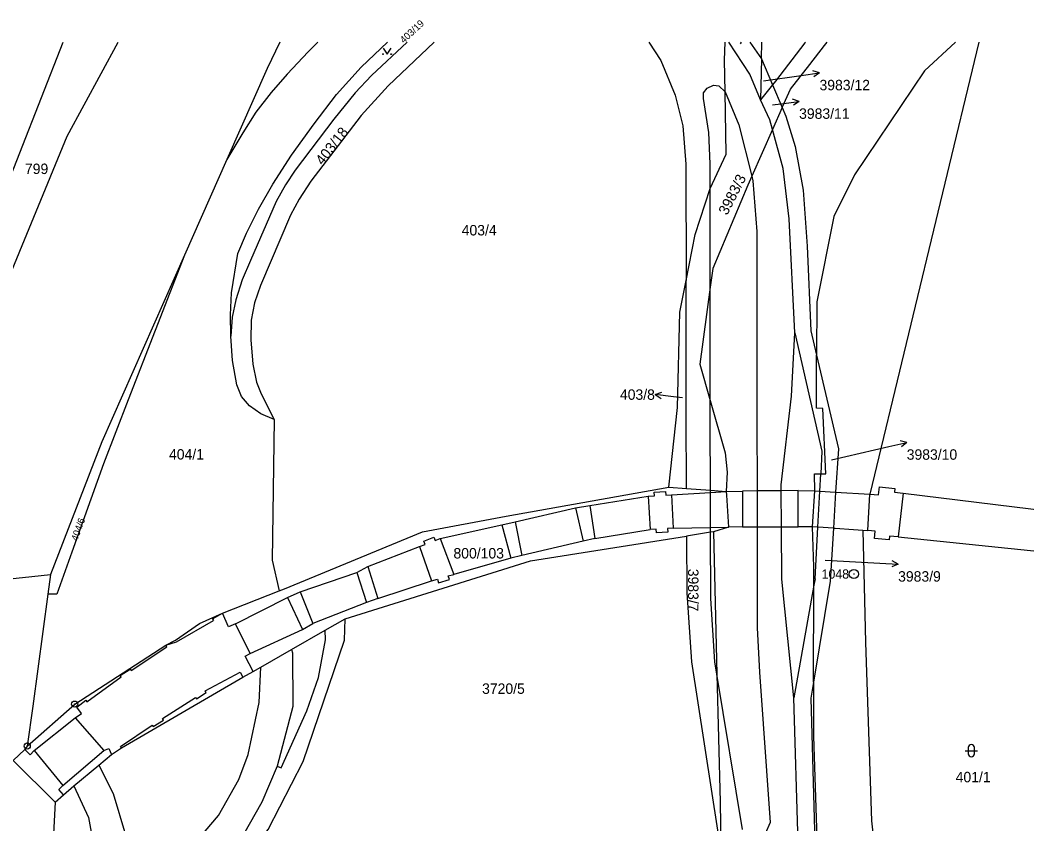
# Model space of a CAD drawing. Extents: x -747779 to -747197, y -965543 to -964919.
# Drawn here: x -747660.7 to -747496.8, y -965049.6 to -964918.7 of the extents above; entities that cross this region are included whole.
import ezdxf

# ---------------------------------------------------------------- set-up
doc = ezdxf.new("R2010")
doc.units = 0
for name, color, linetype in [('Hranice parcel', 7, 'Continuous'), ('Parcelní čísla', 7, 'Continuous'), ('Pop  PČ popisy', 7, 'Continuous'), ('Vnitřní kresba', 7, 'Continuous'), ('Značky bodu BP', 7, 'Continuous'), ('Značky kultur', 7, 'Continuous')]:
    doc.layers.add(name, color=color, linetype=linetype)

msp = doc.modelspace()

# ---------------------------------------------------------------- linework, layer by layer
at = {"layer": 'Hranice parcel'}
for p, q in [((-747539.99, -964924.99), (-747540.12, -964931.65)), ((-747539.99, -964924.99), (-747538.17, -964929.23)), ((-747538.17, -964929.23), (-747540.12, -964931.65)), ((-747538.17, -964929.23), (-747536.59, -964932.93)), ((-747536.59, -964932.93), (-747538.19, -964936.51)), ((-747626.99, -964941.37), (-747633.9, -964956.97)), ((-747555.06, -964994.76), (-747552.2, -964994.96))]:
    msp.add_line(p, q, dxfattribs=at)
for points in [[(-747681.46, -965000.29), (-747680.95, -964999.09), (-747672.35, -964972.3), (-747664.27, -964949.29), (-747653.66, -964922.25)], [(-747679.51, -965002.12), (-747679.42, -965001.69), (-747652.99, -964937.55), (-747644.69, -964922.25)], [(-747618.4, -964922.25), (-747620.44, -964926.57), (-747626.99, -964941.37)], [(-747612.2, -964922.25), (-747613.78, -964923.86), (-747617.18, -964927.46), (-747619.82, -964930.48), (-747622.28, -964933.68), (-747624.41, -964937.05), (-747626.99, -964941.37)], [(-747626.36, -964970.12), (-747626.42, -964966.65), (-747626.24, -964963.07), (-747625.23, -964956.7), (-747623.82, -964953.37), (-747621.85, -964949.45), (-747619.54, -964945.4), (-747616.5, -964940.69), (-747612.82, -964935.54), (-747609.15, -964930.81), (-747605.17, -964926.31), (-747600.85, -964922.25)], [(-747597.67, -964922.25), (-747603.48, -964927.68), (-747606.12, -964930.54), (-747609.57, -964934.8), (-747615.87, -964943.12), (-747617.46, -964945.5), (-747618.98, -964948.21), (-747623.16, -964957.81), (-747624.52, -964960.99), (-747625.54, -964964.21), (-747626.17, -964967.05), (-747626.36, -964970.12)], [(-747593.26, -964922.25), (-747600.76, -964929.37), (-747605.14, -964934.21), (-747613.35, -964944.89), (-747615.24, -964947.83), (-747616.64, -964950.46), (-747621.52, -964961.9), (-747622.5, -964964.72), (-747623.07, -964967.52), (-747623.12, -964970.73), (-747622.76, -964974.72), (-747622.16, -964977.65), (-747621.45, -964979.51), (-747619.33, -964983.74)], [(-747558.33, -964922.25), (-747556.34, -964925.25), (-747554.01, -964930.9), (-747552.8, -964935.88), (-747552.27, -964942.11), (-747552.26, -964961.06)], [(-747552.26, -964961.06), (-747550.79, -964953.59), (-747548.32, -964946.08), (-747545.72, -964940.48), (-747545.91, -964930.33), (-747546, -964925.2), (-747545.87, -964922.25)], [(-747540.12, -964931.65), (-747541.88, -964927.49), (-747545.31, -964922.25)], [(-747541.85, -964922.25), (-747539.99, -964924.99)], [(-747539.99, -964924.99), (-747539.94, -964922.25)], [(-747532.8, -964922.25), (-747532.89, -964922.36), (-747537.7, -964928.64), (-747538.17, -964929.23)], [(-747536.59, -964932.93), (-747535.26, -964929.94), (-747532.12, -964925.89), (-747529.73, -964922.8), (-747529.3, -964922.25)], [(-747508.39, -964922.25), (-747513.42, -964926.91), (-747524.82, -964943.86), (-747525.34, -964944.9), (-747527.79, -964949.82), (-747528.21, -964950.66), (-747530.97, -964964.56), (-747531.01, -964973.24)], [(-747538.19, -964936.51), (-747538.62, -964934.92), (-747540.12, -964931.65)], [(-747536.59, -964932.93), (-747535.99, -964934.33), (-747534.51, -964939.26), (-747533.21, -964946.39), (-747532.52, -964955.47), (-747531.93, -964969.25), (-747531.01, -964973.24)], [(-747538.19, -964936.51), (-747541.56, -964944.09), (-747542.21, -964945.54), (-747547.91, -964959.15), (-747548.32, -964962.14), (-747550.02, -964974.69), (-747548.31, -964980.62), (-747545.86, -964989.14), (-747545.55, -964992.32), (-747545.72, -964995.42)], [(-747513.05, -965203.34), (-747515.92, -965191.31), (-747520.21, -965170.52), (-747525.67, -965137.7), (-747528.61, -965118.1), (-747531.3, -965092.39), (-747532.87, -965073.71), (-747533.98, -965052.7), (-747534.7, -965029.05), (-747536.67, -965009.71), (-747536.72, -965001.18), (-747536.76, -964995.31), (-747536.77, -964994.35), (-747535.07, -964979.91), (-747534.55, -964969.6), (-747535.47, -964951.02), (-747536.46, -964942.86), (-747538.19, -964936.51)], [(-747633.9, -964956.97), (-747638.69, -964969.23), (-747643.08, -964980.52), (-747647.08, -964990.95), (-747652.25, -965005.33), (-747654.67, -965012.15), (-747656.14, -965012.16)], [(-747633.9, -964956.97), (-747647.36, -964987.37), (-747655.7, -965008.96), (-747656.14, -965012.16)], [(-747555.06, -964994.76), (-747553.66, -964981.74), (-747553.27, -964966.23), (-747552.26, -964961.06)], [(-747552.2, -964994.96), (-747552.24, -964983.14), (-747552.26, -964961.06)], [(-747619.33, -964983.74), (-747621.48, -964982.79), (-747623.33, -964981.51), (-747624.65, -964979.96), (-747625.39, -964978.05), (-747626.07, -964974.09), (-747626.36, -964970.12)], [(-747531.69, -965001.21), (-747531.31, -964995.33), (-747531.36, -964992.55), (-747530.33, -964992.56), (-747529.52, -964992.56), (-747530.01, -964981.9), (-747531.04, -964981.86), (-747531.01, -964973.24)], [(-747531.01, -964973.24), (-747527.46, -964988.49), (-747527.9, -964995.54), (-747528.26, -965001.42)], [(-747619.33, -964983.74), (-747619.61, -965006.6), (-747618.52, -965011.63)], [(-747618.52, -965011.63), (-747617.61, -965011.27), (-747595.16, -965002.01), (-747581.54, -964999.46), (-747555.06, -964994.76)], [(-747552.2, -964994.96), (-747548.28, -964995.24), (-747545.72, -964995.42)], [(-747545.72, -964995.42), (-747545.68, -964996.06), (-747545.36, -965001.27), (-747547.8, -965002.01)], [(-747547.8, -965002.01), (-747548.27, -965002.08), (-747552.17, -965002.7)], [(-747547.8, -965002.01), (-747547.22, -965025.19), (-747546.7, -965046.04), (-747546.54, -965056.95)], [(-747531.5, -965026.48), (-747531.44, -965010.69), (-747531.43, -965007.69), (-747531.69, -965001.21)], [(-747528.26, -965001.42), (-747530.8, -965001.26), (-747531.69, -965001.21)], [(-747528.26, -965001.42), (-747528.79, -965010.06), (-747531.5, -965026.48)], [(-747528.26, -965001.42), (-747527.97, -965001.44), (-747524.98, -965001.63), (-747523.47, -965001.72), (-747523.04, -965020.06), (-747522.04, -965049.05), (-747520.57, -965062.57), (-747513.95, -965097.88), (-747505.52, -965130.78), (-747493.77, -965163.26), (-747487.95, -965176.49)], [(-747607.76, -965016.2), (-747577.6, -965006.72), (-747552.17, -965002.7)], [(-747552.17, -965002.7), (-747552.14, -965011.96), (-747551.37, -965023.19), (-747547.13, -965050.59), (-747546.54, -965056.95)], [(-747659.51, -965036.9), (-747651.78, -965030.07), (-747636.97, -965020.46), (-747635.38, -965019.64), (-747631.49, -965016.92), (-747627.72, -965015.27), (-747618.52, -965011.63)], [(-747656.14, -965012.16), (-747658.62, -965030.4), (-747659.51, -965036.9)], [(-747654.95, -965046.06), (-747653.6, -965044.82), (-747651.92, -965043.4), (-747647.86, -965039.99), (-747645.81, -965038.26), (-747644.18, -965037.21), (-747624.43, -965025.68), (-747622.72, -965024.74), (-747621.47, -965024.03), (-747616.49, -965021.18), (-747610.98, -965018.03), (-747607.76, -965016.2)], [(-747638.39, -965075.25), (-747631.31, -965064.26), (-747625.79, -965057.37), (-747620.28, -965050.49), (-747614.58, -965039.39), (-747607.88, -965019.66), (-747607.76, -965016.2)], [(-747531.5, -965026.48), (-747531.53, -965035.27), (-747530.45, -965066.92)], [(-747659.51, -965036.9), (-747659.91, -965037.48), (-747661.82, -965039.23), (-747654.95, -965046.06)], [(-747654.95, -965046.06), (-747656.17, -965068.62), (-747656.64, -965070.56)]]:
    msp.add_lwpolyline(points, dxfattribs=at)
at = {"layer": 'Pop  PČ popisy'}
for p, q in [((-747543.4, -964922.54), (-747543.22, -964922.25)), ((-747539.65, -964928.55), (-747533.5, -964927.69)), ((-747533.5, -964927.69), (-747530.53, -964927.27)), ((-747530.53, -964927.27), (-747531.59, -964926.92)), ((-747530.53, -964927.27), (-747531.45, -964927.91)), ((-747533.85, -964931.93), (-747534.91, -964931.56)), ((-747538.17, -964932.47), (-747536.83, -964932.3)), ((-747536.83, -964932.3), (-747533.85, -964931.93)), ((-747533.85, -964931.93), (-747534.78, -964932.55)), ((-747557.26, -964979.65), (-747556.2, -964979.28)), ((-747554.28, -964980.02), (-747557.26, -964979.65)), ((-747557.26, -964979.65), (-747556.33, -964980.27)), ((-747552.81, -964980.19), (-747554.28, -964980.02)), ((-747519.25, -964988.11), (-747516.33, -964987.44)), ((-747516.33, -964987.44), (-747517.41, -964987.17)), ((-747516.33, -964987.44), (-747517.19, -964988.15)), ((-747528.58, -964990.26), (-747519.25, -964988.11)), ((-747529.59, -965006.64), (-747520.73, -965007.13)), ((-747520.73, -965007.13), (-747517.73, -965007.29)), ((-747517.73, -965007.29), (-747518.71, -965006.73)), ((-747517.73, -965007.29), (-747518.76, -965007.73))]:
    msp.add_line(p, q, dxfattribs=at)
at = {"layer": 'Vnitřní kresba'}
for p, q in [((-747504.6, -964922.25), (-747522.32, -964995.87)), ((-747549.39, -964930.54), (-747548.81, -964929.74)), ((-747548.81, -964929.74), (-747547.79, -964929.28)), ((-747547.79, -964929.28), (-747546.93, -964929.4)), ((-747546.93, -964929.4), (-747545.91, -964930.33)), ((-747549.42, -964931.45), (-747549.39, -964930.54)), ((-747548.55, -964936.99), (-747549.42, -964931.45)), ((-747545.91, -964930.33), (-747543.68, -964935.74)), ((-747543.68, -964935.74), (-747541.56, -964944.09)), ((-747548.32, -964942.08), (-747548.55, -964936.99)), ((-747548.32, -964946.08), (-747548.32, -964942.08)), ((-747541.56, -964944.09), (-747541.37, -964944.85)), ((-747541.37, -964944.85), (-747540.75, -964953.1)), ((-747548.32, -964962.14), (-747548.32, -964946.08)), ((-747540.75, -964953.1), (-747540.71, -964983.81)), ((-747548.31, -964980.62), (-747548.32, -964962.14)), ((-747534.55, -964969.6), (-747530.13, -964988.87)), ((-747548.31, -964984.22), (-747548.31, -964980.62)), ((-747548.28, -964995.24), (-747548.31, -964984.22)), ((-747540.71, -964983.81), (-747540.69, -964995.35)), ((-747530.13, -964988.87), (-747530.33, -964992.56)), ((-747530.48, -964995.38), (-747530.33, -964992.56)), ((-747557.43, -964995.56), (-747555.6, -964995.46)), ((-747557.4, -964996.16), (-747557.43, -964995.56)), ((-747555.6, -964995.46), (-747555.57, -964996.06)), ((-747554.65, -964996.01), (-747548.28, -964995.59)), ((-747548.28, -964995.59), (-747548.28, -964995.24)), ((-747548.28, -964995.59), (-747545.72, -964995.42)), ((-747548.27, -965001.32), (-747548.28, -964995.59)), ((-747545.72, -964995.42), (-747543.05, -964995.37)), ((-747540.69, -964995.35), (-747543.05, -964995.37)), ((-747543.05, -964995.37), (-747543.05, -965001.2)), ((-747536.76, -964995.31), (-747540.69, -964995.35)), ((-747540.69, -964995.35), (-747540.68, -965001.19)), ((-747534.01, -964995.28), (-747536.76, -964995.31)), ((-747534.01, -964995.28), (-747531.31, -964995.33)), ((-747534, -965001.17), (-747534.01, -964995.28)), ((-747531.31, -964995.33), (-747530.48, -964995.38)), ((-747530.8, -965001.26), (-747530.48, -964995.38)), ((-747530.48, -964995.38), (-747527.9, -964995.54)), ((-747527.9, -964995.54), (-747522.32, -964995.87)), ((-747520.9, -964996), (-747520.78, -964994.66)), ((-747520.78, -964994.66), (-747518.27, -964994.94)), ((-747518.27, -964994.94), (-747518.34, -964995.57)), ((-747518.34, -964995.57), (-747516.92, -964995.72)), ((-747516.92, -964995.72), (-747517.7, -965002.84)), ((-747516.92, -964995.72), (-747483.5, -964999.8)), ((-747567.93, -964997.71), (-747558.4, -964996.22)), ((-747558.4, -964996.22), (-747557.4, -964996.16)), ((-747558.4, -964996.22), (-747558.11, -965001.64)), ((-747555.57, -964996.06), (-747554.65, -964996.01)), ((-747554.65, -964996.01), (-747554.35, -965001.43)), ((-747522.65, -965001.77), (-747522.32, -964995.87)), ((-747522.32, -964995.87), (-747520.9, -964996)), ((-747580.1, -965000.39), (-747570.24, -964998.12)), ((-747570.24, -964998.12), (-747567.93, -964997.71)), ((-747570.24, -964998.12), (-747569.01, -965003.51)), ((-747567.93, -964997.71), (-747567.11, -965003.07)), ((-747582.26, -965000.88), (-747580.1, -965000.39)), ((-747580.1, -965000.39), (-747579, -965005.85)), ((-747592.28, -965003.07), (-747582.26, -965000.88)), ((-747582.26, -965000.88), (-747580.76, -965006.28)), ((-747567.11, -965003.07), (-747558.11, -965001.64)), ((-747557.11, -965001.58), (-747558.11, -965001.64)), ((-747557.07, -965002.18), (-747557.11, -965001.58)), ((-747555.24, -965002.08), (-747557.07, -965002.18)), ((-747554.35, -965001.43), (-747555.27, -965001.48)), ((-747555.27, -965001.48), (-747555.24, -965002.08)), ((-747554.35, -965001.43), (-747548.27, -965001.32)), ((-747548.27, -965001.32), (-747545.36, -965001.27)), ((-747548.27, -965002.08), (-747548.27, -965001.32)), ((-747548.24, -965012.85), (-747548.27, -965002.08)), ((-747543.05, -965001.2), (-747545.36, -965001.27)), ((-747543.05, -965001.2), (-747540.68, -965001.19)), ((-747540.68, -965001.19), (-747536.72, -965001.18)), ((-747540.68, -965001.19), (-747540.66, -965017.65)), ((-747536.72, -965001.18), (-747534, -965001.17)), ((-747531.69, -965001.21), (-747534, -965001.17)), ((-747531.26, -965009.67), (-747530.8, -965001.26)), ((-747523.47, -965001.72), (-747522.65, -965001.77)), ((-747521.48, -965001.88), (-747522.65, -965001.77)), ((-747521.6, -965003.09), (-747521.48, -965001.88)), ((-747594.96, -965003.52), (-747593.32, -965002.86)), ((-747594.74, -965004.05), (-747594.96, -965003.52)), ((-747593.32, -965002.86), (-747593.1, -965003.4)), ((-747593.1, -965003.4), (-747592.28, -965003.07)), ((-747592.28, -965003.07), (-747590.07, -965008.94)), ((-747569.01, -965003.51), (-747579, -965005.85)), ((-747567.11, -965003.07), (-747569.01, -965003.51)), ((-747519.2, -965003.29), (-747521.6, -965003.09)), ((-747519.14, -965002.69), (-747519.2, -965003.29)), ((-747517.7, -965002.84), (-747519.14, -965002.69)), ((-747517.7, -965002.84), (-747483.98, -965006.3)), ((-747604.05, -965007.65), (-747595.65, -965004.42)), ((-747595.65, -965004.42), (-747594.74, -965004.05)), ((-747595.65, -965004.42), (-747593.68, -965010)), ((-747580.76, -965006.28), (-747590.07, -965008.94)), ((-747579, -965005.85), (-747580.76, -965006.28)), ((-747615.1, -965011.79), (-747605.87, -965008.63)), ((-747605.87, -965008.63), (-747604.05, -965007.65)), ((-747605.87, -965008.63), (-747604.26, -965013.51)), ((-747604.05, -965007.65), (-747602.44, -965012.85)), ((-747665.29, -965009.95), (-747655.7, -965008.96)), ((-747602.44, -965012.85), (-747593.68, -965010)), ((-747593.68, -965010), (-747592.71, -965009.72)), ((-747592.71, -965009.72), (-747592.54, -965010.29)), ((-747592.54, -965010.29), (-747590.79, -965009.77)), ((-747590.96, -965009.2), (-747590.07, -965008.94)), ((-747590.79, -965009.77), (-747590.96, -965009.2)), ((-747531.26, -965009.67), (-747531.44, -965010.69)), ((-747617.14, -965012.71), (-747615.1, -965011.79)), ((-747615.1, -965011.79), (-747613, -965016.92)), ((-747531.44, -965010.69), (-747534.7, -965029.05)), ((-747625.62, -965016.99), (-747617.14, -965012.71)), ((-747617.14, -965012.71), (-747614.7, -965017.92)), ((-747604.26, -965013.51), (-747613, -965016.92)), ((-747602.44, -965012.85), (-747604.26, -965013.51)), ((-747547.55, -965023.19), (-747548.24, -965012.85)), ((-747629.36, -965016.2), (-747627.72, -965015.27)), ((-747626.73, -965017.49), (-747627.72, -965015.27)), ((-747635.23, -965019.9), (-747629.21, -965016.46)), ((-747629.36, -965016.2), (-747629.21, -965016.46)), ((-747625.62, -965016.99), (-747626.73, -965017.49)), ((-747623.23, -965021.83), (-747625.62, -965016.99)), ((-747614.7, -965017.92), (-747613, -965016.92)), ((-747623.23, -965021.83), (-747614.7, -965017.92)), ((-747610.94, -965019.58), (-747610.98, -965018.03)), ((-747540.66, -965017.65), (-747540.29, -965024.86)), ((-747636.97, -965020.46), (-747635.23, -965019.9)), ((-747612.11, -965025.74), (-747610.94, -965019.58)), ((-747642.6, -965024.61), (-747636.8, -965020.72)), ((-747636.8, -965020.72), (-747636.97, -965020.46)), ((-747624.04, -965022.26), (-747623.23, -965021.83)), ((-747616.49, -965021.18), (-747616.34, -965021.72)), ((-747616.34, -965021.72), (-747616.27, -965030.48)), ((-747622.72, -965024.74), (-747624.04, -965022.26)), ((-747547.22, -965025.19), (-747547.55, -965023.19)), ((-747644.37, -965025.4), (-747642.77, -965024.36)), ((-747642.77, -965024.36), (-747642.6, -965024.61)), ((-747630.54, -965027.93), (-747624.85, -965024.89)), ((-747624.85, -965024.89), (-747624.43, -965025.68)), ((-747621.74, -965029.81), (-747621.47, -965024.03)), ((-747543.06, -965050.51), (-747547.22, -965025.19)), ((-747540.29, -965024.86), (-747538.54, -965049.36)), ((-747649.78, -965029.68), (-747644.19, -965025.64)), ((-747644.19, -965025.64), (-747644.37, -965025.4)), ((-747613.98, -965031.17), (-747612.11, -965025.74)), ((-747531.5, -965026.48), (-747531.93, -965029.1)), ((-747631.93, -965029.22), (-747630.4, -965028.2)), ((-747630.4, -965028.2), (-747630.54, -965027.93)), ((-747651.42, -965030.58), (-747649.96, -965029.43)), ((-747649.96, -965029.43), (-747649.78, -965029.68)), ((-747637.48, -965032.43), (-747632.09, -965028.97)), ((-747632.09, -965028.97), (-747631.93, -965029.22)), ((-747623.53, -965038.25), (-747621.74, -965029.81)), ((-747531.93, -965029.1), (-747531.31, -965052.62)), ((-747651.71, -965032.3), (-747650.7, -965031.58)), ((-747650.7, -965031.58), (-747651.42, -965030.58)), ((-747616.27, -965030.48), (-747618.82, -965040.15)), ((-747618.17, -965040.45), (-747613.98, -965031.17)), ((-747658.37, -965037.62), (-747651.71, -965032.3)), ((-747651.71, -965032.3), (-747647.03, -965037.64)), ((-747639, -965033.71), (-747637.32, -965032.68)), ((-747637.32, -965032.68), (-747637.48, -965032.43)), ((-747644.34, -965036.97), (-747639.17, -965033.47)), ((-747639.17, -965033.47), (-747639, -965033.71)), ((-747659.91, -965037.48), (-747659.04, -965038.32)), ((-747659.04, -965038.32), (-747658.37, -965037.62)), ((-747658.37, -965037.62), (-747653.69, -965043.34)), ((-747653.69, -965043.34), (-747647.03, -965037.64)), ((-747647.03, -965037.64), (-747646.21, -965037.3)), ((-747646.21, -965037.3), (-747645.81, -965038.26)), ((-747644.18, -965037.21), (-747644.34, -965036.97)), ((-747625.06, -965042.37), (-747623.53, -965038.25)), ((-747647.86, -965039.99), (-747645.5, -965044.62)), ((-747618.82, -965040.15), (-747621.32, -965046.05)), ((-747618.82, -965040.15), (-747618.17, -965040.45)), ((-747628.37, -965048.23), (-747625.06, -965042.37)), ((-747654.38, -965043.96), (-747653.69, -965043.34)), ((-747653.6, -965044.82), (-747654.38, -965043.96)), ((-747651.92, -965043.4), (-747649.51, -965048.56)), ((-747645.5, -965044.62), (-747643.49, -965051.37)), ((-747621.32, -965046.05), (-747624.28, -965051.28)), ((-747649.51, -965048.56), (-747648.13, -965056.14)), ((-747635.12, -965056.13), (-747628.37, -965048.23)), ((-747538.54, -965049.36), (-747539.35, -965051.18))]:
    msp.add_line(p, q, dxfattribs=at)
at = {"layer": 'Značky bodu BP'}
for centre, radius in [((-747524.93, -965008.88), 0.75), ((-747524.93, -965008.88), 0.03), ((-747651.78, -965030.07), 0.5), ((-747651.78, -965030.07), 0.0303), ((-747659.51, -965036.9), 0.5), ((-747659.51, -965036.9), 0.0303)]:
    msp.add_circle(centre, radius, dxfattribs=at)
at = {"layer": 'Značky kultur'}
for p, q in [((-747506.82, -965037.65), (-747504.82, -965037.65)), ((-747506.32, -965037.15), (-747506.32, -965038.15)), ((-747505.32, -965038.15), (-747505.32, -965037.15))]:
    msp.add_line(p, q, dxfattribs=at)
msp.add_lwpolyline([(-747601.59, -964923.22), (-747600.92, -964924.23), (-747600.25, -964923.22)], dxfattribs=at)
for centre in [(-747601.59, -964924.23), (-747600.25, -964924.23)]:
    msp.add_circle(centre, 0.067, dxfattribs=at)
for centre, start, end in [((-747505.82, -965037.15), 0, 180), ((-747505.82, -965038.15), 180, 359.9879)]:
    msp.add_arc(centre, 0.5, start, end, dxfattribs=at)

# ---------------------------------------------------------------- texts
at = {"layer": 'Parcelní čísla'}
for s, height, rotation, p in [('403/19', 1.139, 43, (-747598.2, -964922.53)), ('403/18', 1.7, 52, (-747611.4, -964942.43)), ('3983/3', 1.7, 63, (-747545.56, -964950.55)), ('404/6', 1.139, 70, (-747651.35, -965003.58)), ('3983/7', 1.7, 270, (-747551.93, -965008.03))]:
    msp.add_text(s, height=height, rotation=rotation, dxfattribs=at).set_placement(p)
for s, p in [('3983/12', (-747530.53, -964930.1)), ('3983/11', (-747533.85, -964934.75)), ('799', (-747659.88, -964943.74)), ('403/4', (-747588.78, -964953.74)), ('403/8', (-747563.02, -964980.51)), ('404/1', (-747636.43, -964990.24)), ('3983/10', (-747516.33, -964990.27)), ('800/103', (-747590.12, -965006.35)), ('3983/9', (-747517.73, -965010.12)), ('3720/5', (-747585.46, -965028.4)), ('401/1', (-747508.36, -965042.8))]:
    msp.add_text(s, height=1.7, dxfattribs=at).set_placement(p)
at = {"layer": 'Značky bodu BP'}
msp.add_text('1048', height=1.5, dxfattribs=at).set_placement((-747530.18, -965009.63))

doc.saveas('drawing.dxf')
